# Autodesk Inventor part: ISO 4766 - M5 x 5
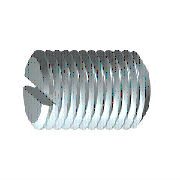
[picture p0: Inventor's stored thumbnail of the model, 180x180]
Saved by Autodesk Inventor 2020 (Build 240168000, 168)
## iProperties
IsCustomPart: 0
Created: 2008-01
Part Number: ISO 4766 - M5 x 5
Material: Stainless Steel, 440C
Description: Slotted Headless Set Screw - Flat Point
Document SubType Name: Modeling
Standard: ISO 4766
Designer: latalom
Standard Revision: First edition 1983-09-01
Standards Organization: ISO
Language: en-US
Size Designation: M5 x 5
Categories: <MemberInstance><Categories><Category DisplayName="Fasteners" InternalName="e4da775c-781d-43d5-af7c-5136215cf5a6" Mnemonic="FSTN"><Category DisplayName="Bolts"
Density: 7.75 g/cm^3
Mass: 0.682426 g
Surface Area: 1.16465 cm^2
Volume: 0.088055 cm^3
Appearance: Steel
Author: latalom
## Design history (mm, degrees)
sketch "Sketch1"
  geometry: L1 (0, 0)-(5, 0); L2 (5, 0)-(5, 2.5); L3 (5, 2.5)-(0, 2.5); L4 (0, -0.5)-(0, 3) reference; L5 (0, 2.5)-(0, 0)
  constraints: 9 end point, 2 parallel, 2 perpendicular, 1 collinear, 1 point on line
  dimensions: "d0" = 5 diameter of L3 L1 (= NND); "d2" = 5 distance from line of L2 L3.end (= NLG)
revolve "Body" sketch "Sketch1" stored, may be unused: angle "d6" = 90 deg
sketch "Sketch2"
  geometry: L1 (5, 2.009)-(5, -2.009) reference; L2 (3.464, 0)-(5.256, 0) reference; L3 (5, 0.4)-(3.72, 0.4); L4 (3.72, 0.4)-(3.72, 0); L5 (3.72, -0.4)-(3.72, 0); L6 (3.72, -0.4)-(5, -0.4)
  constraints: 8 end point, 3 point on line, 2 perpendicular, 1 parallel, 1 symmetric about line, 1 other
  dimensions: "d8" = 0.4 distance between parallel lines of L2 L3 (= 0.5 x SBR); "d9" = 1.28 distance between parallel lines of L1 L4 (= STI)
extrude "Slot1" cut sketch "Sketch2" stored distance "d10" = 5 (= NND); taper "d11" = 0 deg
workaxis "Work Axis1"
workplane "Work Plane1"
body "Solid1"
chamfer "Chamfer1" distance "d3" = 0.49076 (= -0.5 x GD1 + 0.5 x NND); stored, may be unused: angle "d4" = 60 deg (= FAWI), second distance "d34" = 0.49076 (= -0.5 x GD1 + 0.5 x NND)
feature "Thread" dims "d5" = 5 (= NLG), "d7" = 0
chamfer "Chamfer2" distance "d13" = 0.43301 (computed from NND, SPD, FAWI); stored, may be unused: angle "d14" = 60 deg (= FAWI), second distance "d35" = 0.43301 (computed from NND, SPD, FAWI)
other parameters: "NND" = 5 [user parameter; used in 6 equation terms], "NLG" = 5 [user parameter; used in 2 equation terms], "FAWI" = 60 deg [user parameter; used in 4 equation terms], "GD1" = 4.01848 (= THREADDIA - 1.2269 x PTC) [user parameter; used in 2 equation terms], "d1" = 0, "FAWI1" = 45 deg [user parameter], "SPD" = 3.5 [user parameter; used in 2 equation terms], "SBR" = 0.8 [user parameter; used in 1 equation term], "STI" = 1.28 [user parameter; used in 1 equation term], "d15" = 0, "d36" = 90 deg, "d37" = 0, "GUL" = 0.49076 (= 0.61345 x PTC) [user parameter], "TPU" = 12.5 (computed from PTC) [user parameter], "THREADDIA" = 5 [user parameter; used in 1 equation term], "TOA" = 30 deg [user parameter], "PTC" = 0.8 [user parameter; used in 4 equation terms], "GAL" = 0.49076 (= 0.61345 x PTC) [user parameter]
